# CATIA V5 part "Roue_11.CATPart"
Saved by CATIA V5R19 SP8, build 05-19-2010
Part number: CE14_Roue_11
Nomenclature: 70_R11
Bounding box of the stored display mesh (mm): x -12.494 to 12.494, y -12.494 to 12.494, z -5.5 to 2
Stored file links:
  C:\Users\rphgr\Desktop\0_Tapis_TC520B_vitesse\Roue_11.CATPart
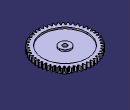
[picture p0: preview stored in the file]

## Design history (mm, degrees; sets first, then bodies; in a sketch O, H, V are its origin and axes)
External parameters (linked from other documents)
  External.Module = 0.5 mm
  External.Z = 48
  External.DiamPrimitif = 24 mm {= External.Module *External.Z}
  External.AnglePression = 20 deg
  External.x = 0
  External.DeportDenture = 0 mm {= External.x *External.Module}
  External.DiamBase = 22.5526 mm {= External.DiamPrimitif *cos(External.AnglePression )}
  External.DiamPied = 22.75 mm {= External.DiamPrimitif -2.5*External.Module +2*External.DeportDenture}
  External.DiamTete = 25 mm {= External.DiamPrimitif +2*External.Module +2*External.DeportDenture}
  External.PhiPrimitif = 0.854 deg {= atan((sin(External.ThetaPrimitif*1rad)-External.ThetaPrimitif*cos(External.ThetaPrimitif*1rad))/(cos(External.ThetaPrimitif*1rad)+External.ThetaPrimitif*sin(External.ThetaPrimitif*1rad)))}
  External.PhiTete = 1.8433 deg {= atan((sin(External.ThetaTete*1rad)-External.ThetaTete*cos(External.ThetaTete*1rad))/(cos(External.ThetaTete*1rad)+External.ThetaTete*sin(External.ThetaTete*1rad)))}
  External.PhiSymetrie = 1.875 deg {= 180*1 deg/(2*External.Z )}
  External.CongePied = 0.19 mm {= 0.38*External.Module}
  External.AlphaCopie = 7.5 deg {= 360*1 deg/External.Z}
  External.AlphaSymetrieCopie = 3.75 deg {= External.AlphaCopie /2}
  External.CoeffQualiteEngrenage = 7
  External.LargeurDenture = 2 mm
  External.ThetaPrimitif = 0.36397 {= sqrt(abs((External.DiamPrimitif*External.DiamPrimitif)/(External.DiamBase *External.DiamBase )-1))}
  External.ThetaTete = 0.478344 {= sqrt(abs((External.DiamTete*External.DiamTete)/(External.DiamBase *External.DiamBase )-1) )}
  External.Di = 23.2763 mm {= (External.DiamBase +External.DiamPrimitif )/2}
  External.Thetai = 0.255358 {= sqrt(abs((External.Di*External.Di)/(External.DiamBase*External.DiamBase)-1))}
  External.Phii = 0.3061 deg {= atan((sin(External.Thetai*1rad)-External.Thetai*cos(External.Thetai*1rad))/(cos(External.Thetai*1rad)+External.Thetai*sin(External.Thetai*1rad)))}
  External.Dj = 24.5 mm {= (External.DiamTete+External.DiamPrimitif)/2}
  External.Thetaj = 0.424444 {= sqrt(abs((External.Dj*External.Dj)/(External.DiamBase*External.DiamBase)-1))}
  External.Phij = 1.3203 deg {= atan((sin(External.Thetaj*1rad)-External.Thetaj*cos(External.Thetaj*1rad))/(cos(External.Thetaj*1rad)+External.Thetaj*sin(External.Thetaj*1rad)))}
  External.Dk = 22.9145 mm {= (External.Di+External.DiamBase)/2}
  External.Thetak = 0.179851 {= sqrt(abs((External.Dk*External.Dk)/(External.DiamBase*External.DiamBase)-1))}
  External.Phik = 0.109 deg {= atan((sin(External.Thetak*1rad)-External.Thetak*cos(External.Thetak*1rad))/(cos(External.Thetak*1rad)+External.Thetak*sin(External.Thetak*1rad)))}
  External.Dl = 23.6382 mm {= (External.DiamPrimitif+External.Di)/2}
  External.Thetal = 0.31398 {= sqrt(abs((External.Dl*External.Dl)/(External.DiamBase*External.DiamBase)-1))}
  External.Phil = 0.5585 deg {= atan((sin(External.Thetal*1rad)-External.Thetal*cos(External.Thetal*1rad))/(cos(External.Thetal*1rad)+External.Thetal*sin(External.Thetal*1rad)))}
  External.Dm = 24.25 mm {= (External.Dj+External.DiamPrimitif)/2}
  External.Thetam = 0.395209 {= sqrt(abs((External.Dm*External.Dm)/(External.DiamBase*External.DiamBase)-1))}
  External.Phim = 1.0794 deg {= atan((sin(External.Thetam*1rad)-External.Thetam*cos(External.Thetam*1rad))/(cos(External.Thetam*1rad)+External.Thetam*sin(External.Thetam*1rad)))}
  External.Dn = 24.75 mm {= (External.DiamTete+External.Dj)/2}
  External.Thetan = 0.452062 {= sqrt(abs((External.Dn*External.Dn)/(External.DiamBase*External.DiamBase)-1))}
  External.Phin = 1.5753 deg {= atan((sin(External.Thetan*1rad)-External.Thetan*cos(External.Thetan*1rad))/(cos(External.Thetan*1rad)+External.Thetan*sin(External.Thetan*1rad)))}
  External.DiametreAlesage = 2 mm
Body1 (main body)
  Sketch1 on xy-plane, origin (0, 0, 0), H (1, 0, 0), V (0, 1, 0)
    construction circle A1 centre (0, 0) radius 12
    construction circle A2 centre (0, 0) radius 11.2763
    construction circle A3 centre (0, 0) radius 11.375
    construction circle A4 centre (0, 0) radius 12.5
    point P1 (11.2763, 0)
    construction line L1 (11.2763, 0) -> (0, 0)
    point P2 (11.9987, 0.1788)
    construction line L2 (11.9987, 0.1788) -> (0, 0)
    point P3 (12.4935, 0.4021)
    construction line L3 (12.4935, 0.4021) -> (0, 0)
    construction line L4 (11.2763, 0) -> (11.2763, 3.9367)
    point P4 (11.2763, 0)
    point P6 (10.554, 0.1788)
    construction line L5 (12.4935, 0.4021) -> (11.9987, 0.1788)
    point P7 (12.2461, 0.2905)
    point P8 (10.3065, 0.2905)
    spline S1 through (10.3065, 0.2905) (10.554, 0.1788) (11.2763, 0) (11.4572, 0.0218) (11.638, 0.0622) (11.8185, 0.1152) (11.9987, 0.1788) (12.1228, 0.2284) (12.2467, 0.2823) (12.3703, 0.3402) (12.4935, 0.4021)
    construction line L6 (0, 0) -> (5.2684, 0.2511)
    spline S2 through (10.2874, 0.6912) (10.5231, 0.8258) (11.2252, 1.0725) (11.4073, 1.0681) (11.5911, 1.045) (11.7759, 1.0094) (11.9613, 0.9632) (12.0896, 0.9257) (12.2181, 0.8839) (12.3466, 0.8379) (12.4751, 0.7881)
    arc A5 centre (11.564, -0.1507) radius 0.19 from (11.5242, 0.035) to (11.374, -0.1483) ccw
    point P11 (11.374, -0.1483)
    arc A6 centre (0, 0) radius 12.5 from (12.4935, 0.4021) to (12.4751, 0.7881) ccw
    point P13 (12.4751, 0.7881)
    arc A7 centre (11.4973, 1.25) radius 0.19 from (11.3084, 1.2294) to (11.4753, 1.0612) ccw
    point P15 (11.3084, 1.2294)
    construction line L7 (0, 0) -> (4.2559, 0.4833)
    construction line L8 (0, 0) -> (5.1251, -0.0913)
    point P19 (11.3024, 1.2835)
    arc A8 centre (0, 0) radius 11.375 from (11.3084, 1.2294) to (11.3024, 1.2835) ccw
    point P20 (11.3732, -0.2027)
    arc A9 centre (0, 0) radius 11.375 from (11.3732, -0.2027) to (11.374, -0.1483) ccw
    line L9 (11.3024, 1.2835) -> (0, 0)
    line L10 (11.3732, -0.2027) -> (0, 0)
    construction circle A10 centre (0, 0) radius 11.6382
    construction line L11 (0, 0) -> (2.5698, 0.0137)
    point P22 (11.638, 0.0622)
    construction circle A11 centre (0, 0) radius 12.25
    construction line L12 (0, 0) -> (4.018, 0.0926)
    point P24 (12.2467, 0.2823)
    point P25 (12.2467, 0.2823)
    point P26 (12.2181, 0.8839)
    point P27 (11.5911, 1.045)
    construction circle A12 centre (0, 0) radius 11.4572
    construction line L13 (0, 0) -> (48.2618, 0.0918)
    point P29 (11.4073, 1.0681)
    construction line L14 (0, 0) -> (63.9059, 3.0461)
    point P31 (11.4572, 0.0218)
    construction circle A13 centre (0, 0) radius 11.8191
    construction line L15 (0, 0) -> (57.3607, 0.5591)
    point P33 (11.8185, 0.1152)
    point P34 (11.7759, 1.0094)
    construction circle A14 centre (0, 0) radius 12.125
    construction line L16 (0, 0) -> (65.6991, 1.2379)
    point P36 (12.1228, 0.2284)
    point P37 (12.0896, 0.9257)
    construction circle A15 centre (0, 0) radius 12.375
    axis line L17 (0, 0) -> (59.3285, 1.6316)
    point P39 (12.3466, 0.8379)
    point P40 (12.3703, 0.3402)
    point P42 (10.3065, 0.2905)
    point P43 (10.554, 0.1788)
    point P44 (11.2763, 0)
    point P45 (11.9987, 0.1788)
    point P46 (12.4935, 0.4021)
    point P47 (12.4751, 0.7881)
    point P48 (10.2874, 0.6912)
    point P49 (11.9613, 0.9632)
    point P50 (11.2252, 1.0725)
    point P51 (10.5231, 0.8258)
    point P52 (11.638, 0.0622)
    point P53 (12.2467, 0.2823)
    point P54 (11.5911, 1.045)
    point P55 (12.2181, 0.8839)
    point P56 (11.4572, 0.0218)
    point P57 (11.4073, 1.0681)
    point P58 (11.8185, 0.1152)
    point P59 (11.7759, 1.0094)
    point P60 (12.1228, 0.2284)
    point P61 (12.0896, 0.9257)
    point P62 (12.3703, 0.3402)
    point P63 (12.3466, 0.8379)
    radius A1 = 12 {= External.DiamPrimitif /2}
    radius A2 = 11.2763 {= External.DiamBase /2}
    radius A3 = 11.375 {= External.DiamPied /2}
    radius A4 = 12.5 {= External.DiamTete /2}
    angle L2 L1 = 0.854 {= External.PhiPrimitif}
    angle L3 L1 = 1.8433 {= External.PhiTete}
    angle L4 L1 = 90
    radius A5 = 0.19 {= External.CongePied}
    radius A7 = 0.19 {= External.CongePied}
    angle L7 L6 = 3.75 {= External.AlphaSymetrieCopie}
    angle L2 L6 = 1.875 {= External.PhiSymetrie}
    radius A10 = 11.6382 {= External.Di /2}
    angle L11 L1 = 0.3061 {= External.Phii}
    radius A11 = 12.25 {= External.Dj /2}
    angle L12 L1 = 1.3203 {= External.Phij}
    radius A12 = 11.4572 {= External.Dk/2}
    angle L13 L1 = 0.109 {= External.Phik}
    angle L14 L2 = 1.875 {= External.PhiSymetrie}
    radius A13 = 11.8191 {= External.Dl /2}
    angle L15 L1 = 0.5585 {= External.Phil}
    radius A14 = 12.125 {= External.Dm /2}
    angle L16 L1 = 1.0794 {= External.Phim}
    radius A15 = 12.375 {= External.Dn/2}
    angle L17 L1 = 1.5753 {= External.Phin}
    coincidence: P1 A2, P1 H, P2 A1, P3 A4, P4 A2, P7 L5, P42 P8, P43 P6, P44 P1, P45 L5, P45 L2, P46 L5, P46 L3, P11 A3, P47 P13, P15 A3, P19 L7, P19 A3, P20 L8, P20 A3, P3 P46, P22 L11, P22 A10, P52 P22, P24 L12, P24 A11, P53 P24, P25 P53, P54 P27, P55 P26, P31 L13, P31 A12, P56 P31, P57 P29, P33 L15, P33 A13, P58 P33, P59 P34, P36 L16, P36 A14, P60 P36, P61 P37, P40 L17, P40 A15, P62 P40, P63 P39, O L9, O L10
    horizontal: L1 H
    tangency: L4 A2, A5 A3, A5 S1, A7 A3, A7 S2, A8 A5, A9 A5
    symmetry: P6 P2 L4, P8 P7 L4, P46 P47 L6, P42 P48 L6, P45 P49 L6, P44 P50 L6, P43 P51 L6, L8 L7 L6, P26 P25 L6, P27 P22 L6, P29 P31 L14, P34 P33 L14, P37 P36 L14, P39 P40 L14
    midpoint: P7 L5
    parallelism: L9 L7, L10 L8
    concentricity: A10 A2, A11 A1
  Pad1: profile Sketch1, direction (0, 0, 1), length 2 {= External.LargeurDenture}
  CircPattern1 "Roue Dentée": of Pad1, instances 48 {= External.Z}, angular step 7.5 {= External.AlphaCopie}, axis from Z axis
  Body2
    Sketch2 on xy-plane, origin (0, 0, 0), H (1, 0, 0), V (0, 1, 0)
      circle A1 centre (0, 0) radius 1
      radius A1 = 1 {= External.DiametreAlesage /2}
    Pad2: profile Sketch2, direction (0, 0, 1), length 4 {= 2*External.LargeurDenture}
  Remove1: tool Body2
  Sketch3 on face of CircPattern1, origin (0, 0, 2), H (1, 0, 0), V (0, -1, 0)
    circle A1 centre (0, 0) radius 2.5
    circle A2 centre (0, 0) radius 10
    radius A2 = 10
    radius A1 = 2.5
  Pocket1: profile Sketch3, direction (0, 0, -1), length 0.7
  Sketch4 on face of CircPattern1, origin (0, 0, 0), H (1, 0, 0), V (0, -1, 0)
    circle A1 centre (0, 0) radius 5
    circle A2 centre (0, 0) radius 4
    distance A2 A1 = 1
    radius A1 = 5
  Pad3: profile Sketch4, direction (0, 0, -1), length 5.5
  Sketch5 on face of CircPattern1, origin (0, 0, 0), H (1, 0, 0), V (0, -1, 0)
    circle A1 centre (0, 0) radius 2.15
    circle A2 centre (0, 0) radius 1
    reference projected circle E1 centre (0, 0) radius 1 from edge [face of Pad2 from Sketch2.A1 | face of CircPattern1]
    radius A1 = 2.15
    coincidence: A2 E1
  Pad4: profile Sketch5, direction (0, 0, -1), length 2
